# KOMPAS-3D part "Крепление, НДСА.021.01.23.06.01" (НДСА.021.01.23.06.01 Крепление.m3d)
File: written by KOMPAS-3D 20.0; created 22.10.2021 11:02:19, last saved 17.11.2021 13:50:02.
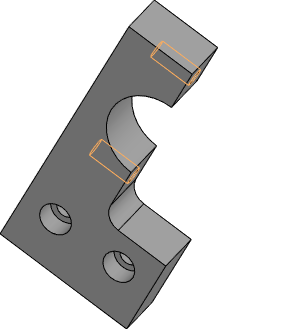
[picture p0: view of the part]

Document properties: Полное имя файла: C:\Users\s.pischagina\Desktop\PLM\НДСА.021.01.23.06.01 Крепление.m3d

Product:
- Part/product: Крепление  | designation НДСА.021.01.23.06.01
    Масса: 0.192777
    additional columns: <item xmlns="http://appius.ru/pdm" xmlns:xs="http://www.w3.org/2001/XMLSchema" x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; <item xmlns="http://appius.ru/pdm" xmlns:xs="http://www.w3.org/2001/XMLSchema" x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; <item xmlns="http://appius.ru/pdm" xmlns:xs="http://www.w3.org/2001/XMLSchema" x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
    source file: НДСА.021.01.23.06.01 Крепление.cdw

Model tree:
1. Эскиз:1
2. Элемент выдавливания:1
     Расстояние 1 = 14
3. Эскиз:2  (with: Элемент выдавливания:1)
4. Отверстие:1  (with: Элемент выдавливания:1)  (labels: M5)
     Глубина выреза = 15; Диаметр отверстия = 4.13397; Угол конуса дна = 118; Расстояние 1 = 7; Расстояние 2 = 6.5
5. M5  (with: Элемент выдавливания:1)  (labels: M5; cil0_24705-2004 coarse)
     Длина резьбы = 12; Шаг резьбы = 0.8; Номинальный диаметр резьбы = 5
6. Отверстие:2  (with: Элемент выдавливания:1, M5)  (labels: M5; cil0_24705-2004 coarse)
     Глубина выреза = 15; Диаметр отверстия = 4.13397; Угол конуса дна = 118; Расстояние 1 = 7; Расстояние 2 = 6.5; Длина резьбы = 12; Шаг резьбы = 0.8; Номинальный диаметр резьбы = 5
7. Эскиз:3  (with: Элемент выдавливания:1)
8. Элемент выдавливания:2

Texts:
  НДСА.021.01.23.06.01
